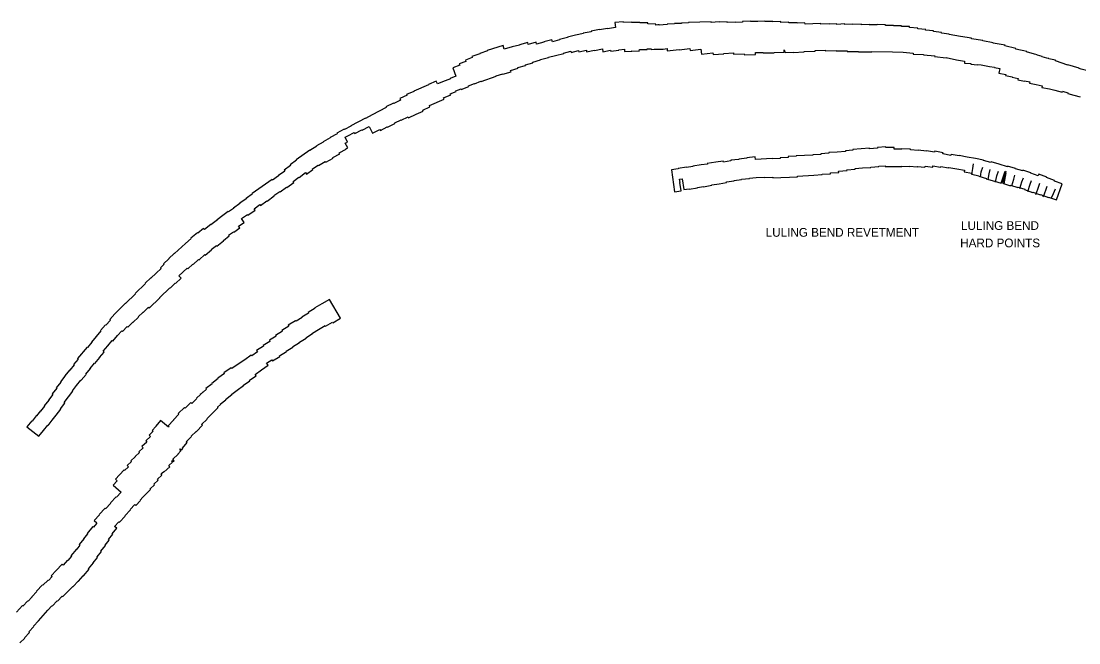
# Model space of a CAD drawing. Extents: x 2650582 to 3923188, y 277893 to 989177.
# Drawn here: x 3605630 to 3624994, y 526152 to 537540 of the extents above; entities that cross this region are included whole.
import ezdxf

# ---------------------------------------------------------------- set-up
doc = ezdxf.new("R2010")
doc.units = 0
doc.layers.add('Level 3', color=7, linetype='Continuous')

msp = doc.modelspace()

# ---------------------------------------------------------------- linework, layer by layer
at = {"layer": 'Level 3'}
msp.add_line((3623624, 534559), (3623666, 534762), dxfattribs=at)
for points in [[(3622480, 537319), (3622482, 537330), (3622332, 537353), (3622333, 537365), (3622189, 537376), (3622190, 537389), (3622045, 537400), (3622046, 537413), (3621895, 537423), (3621895, 537441), (3621748, 537443), (3621748, 537452), (3621602, 537456), (3621602, 537458), (3621457, 537461), (3621457, 537475), (3621301, 537479), (3621301, 537474), (3621157, 537474), (3621157, 537476), (3621013, 537475), (3621012, 537482), (3620858, 537480), (3620858, 537484), (3620712, 537477), (3620712, 537489), (3620565, 537481), (3620565, 537492), (3620420, 537484), (3620420, 537492), (3620273, 537484), (3620272, 537495), (3620127, 537488), (3620127, 537493), (3619981, 537486), (3619980, 537508), (3619835, 537503), (3619835, 537512), (3619687, 537506), (3619687, 537521), (3619540, 537517), (3619540, 537532), (3619393, 537525), (3619392, 537536), (3619247, 537532), (3619247, 537539), (3619116, 537534), (3619116, 537536), (3618985, 537531), (3618985, 537540), (3618838, 537534), (3618838, 537524), (3618703, 537518), (3618703, 537524), (3618558, 537517), (3618557, 537527), (3618411, 537519), (3618411, 537525), (3618265, 537518), (3618264, 537526), (3617848, 537513), (3617848, 537507), (3617717, 537504), (3617717, 537498), (3617589, 537495), (3617589, 537488), (3617455, 537483), (3617456, 537478), (3617310, 537469), (3617309, 537473), (3617309, 537473), (3617309, 537474), (3617287, 537471), (3617249, 537468)], [(3617249, 537468), (3617250, 537486), (3617103, 537491), (3617103, 537507), (3616958, 537510), (3616958, 537514), (3616807, 537517), (3616807, 537524), (3616655, 537516), (3616653, 537530), (3616500, 537513), (3616511, 537424), (3616367, 537400), (3616365, 537408), (3616217, 537381), (3616216, 537384), (3616064, 537355), (3616066, 537347), (3615921, 537320), (3615923, 537311), (3615782, 537283), (3615781, 537286), (3615630, 537248), (3615632, 537241), (3615485, 537203), (3615486, 537199), (3615357, 537164), (3615348, 537197), (3615198, 537158), (3615198, 537157), (3615066, 537121), (3615057, 537154), (3614913, 537115), (3614905, 537146), (3614756, 537106), (3614756, 537103), (3614622, 537067), (3614621, 537069), (3614476, 537029), (3614457, 537094), (3614163, 537005), (3614166, 536994), (3614025, 536947), (3614026, 536941), (3613880, 536891), (3613886, 536873), (3613764, 536824), (3613772, 536802), (3613652, 536756), (3613659, 536735), (3613532, 536687), (3613590, 536535), (3613486, 536489), (3613488, 536484), (3613391, 536446), (3613390, 536449), (3613251, 536391), (3613230, 536440), (3613086, 536378), (3613087, 536376), (3612820, 536258), (3612822, 536253), (3612688, 536198)], [(3624282, 536903), (3624232, 536919), (3624233, 536923), (3624184, 536934), (3624038, 536978), (3624040, 536983), (3623839, 537024), (3623842, 537041), (3623640, 537086), (3623643, 537097), (3623426, 537138), (3623427, 537142), (3623234, 537177), (3623235, 537185), (3623030, 537218), (3623031, 537226), (3622828, 537256), (3622829, 537261), (3622620, 537293), (3622621, 537299), (3622480, 537319)], [(3612063, 535485), (3612196, 535555), (3612207, 535535), (3612333, 535601), (3612335, 535598), (3612474, 535667), (3612470, 535675), (3612585, 535733), (3612588, 535726), (3612713, 535790), (3612722, 535771), (3612860, 535836), (3612991, 535892), (3612983, 535912), (3613114, 535970), (3613105, 535995), (3613375, 536110), (3613364, 536138), (3613494, 536189), (3613487, 536208), (3613594, 536253), (3613590, 536263), (3613683, 536301), (3613688, 536286), (3613825, 536340), (3613821, 536353), (3613930, 536396), (3613931, 536394), (3614047, 536441), (3614049, 536436), (3614325, 536530), (3614324, 536536), (3614447, 536577), (3614450, 536570), (3614599, 536613), (3614592, 536638), (3614729, 536677), (3614726, 536689), (3614865, 536728), (3614863, 536739), (3615000, 536776), (3614996, 536790), (3615141, 536831), (3615140, 536835), (3615283, 536874), (3615282, 536878), (3615412, 536912), (3615413, 536910), (3615563, 536948), (3615561, 536955), (3615691, 536990), (3615697, 536968), (3615833, 537003), (3615839, 536977), (3615978, 537006), (3615983, 536980), (3616124, 537008), (3616125, 537004), (3616271, 537032), (3616282, 536978), (3616422, 537006), (3616425, 536989), (3616572, 537010), (3616572, 537016), (3616674, 537029), (3616676, 536983), (3616809, 536989), (3616809, 536994), (3616946, 536990), (3616948, 537021), (3617092, 537018), (3617093, 537033), (3617163, 537031), (3617164, 537023), (3617217, 537029), (3617384, 537025), (3617384, 537029), (3617455, 537036)], [(3617455, 537036), (3617459, 536998), (3617676, 537020), (3617677, 537012), (3617875, 537037), (3617879, 537004), (3618075, 537025), (3618086, 536938), (3618294, 536958), (3618298, 536927), (3618493, 536943), (3618493, 536946), (3618673, 536959), (3618674, 536936), (3618869, 536944), (3618870, 536923), (3619074, 536926), (3619074, 536963)], [(3619074, 536963), (3619216, 536968), (3619216, 536960), (3619419, 536961), (3619419, 536966), (3619597, 536971), (3619597, 537013), (3619615, 536966), (3619764, 536972), (3619764, 536967), (3619963, 536975), (3619963, 536981), (3620169, 536987), (3620169, 537000), (3620350, 537006), (3620350, 536998), (3620551, 537000), (3620551, 536994), (3620754, 536996), (3620755, 536985), (3620958, 536986), (3620958, 536975), (3621174, 536975), (3621174, 536980), (3621205, 536978), (3621205, 536983), (3621580, 536975), (3621581, 536980), (3621775, 536969), (3621775, 536974), (3621961, 536955), (3621960, 536937), (3622153, 536926), (3622153, 536922), (3622355, 536905), (3622354, 536895), (3622567, 536867), (3622568, 536871), (3622756, 536834), (3622755, 536829), (3622902, 536804), (3622900, 536771), (3623017, 536763), (3623016, 536752), (3623139, 536739), (3623139, 536744), (3623207, 536737), (3623359, 536709), (3623360, 536712), (3623450, 536698), (3623449, 536690), (3623549, 536675)], [(3625365, 536560), (3625256, 536591), (3625256, 536591), (3625158, 536626), (3625158, 536628), (3625039, 536663), (3625038, 536659), (3624998, 536673), (3624999, 536678), (3624794, 536742), (3624791, 536736), (3624564, 536810), (3624567, 536823), (3624445, 536849), (3624445, 536853), (3624408, 536861), (3624322, 536889), (3624323, 536894), (3624282, 536903)], [(3623549, 536675), (3623530, 536588), (3623657, 536562), (3623654, 536547), (3623774, 536522), (3623772, 536512), (3623881, 536489), (3623876, 536466), (3623998, 536440), (3624000, 536449), (3624097, 536428), (3624092, 536406), (3624214, 536380), (3624214, 536381), (3624325, 536358), (3624318, 536327), (3624455, 536298), (3624456, 536302), (3624553, 536278), (3624552, 536274), (3624687, 536236), (3624693, 536256), (3624795, 536226), (3624793, 536217), (3624902, 536186), (3625021, 536152)], [(3612688, 536198), (3612695, 536182), (3612563, 536122), (3612575, 536094), (3612451, 536033), (3612448, 536040), (3612309, 535970), (3612314, 535958), (3612054, 535825), (3612055, 535823), (3611934, 535759), (3611932, 535763), (3611665, 535623), (3611667, 535618), (3611548, 535557), (3611546, 535560), (3611411, 535486), (3611415, 535477), (3611287, 535409), (3611290, 535402), (3611160, 535330), (3611161, 535326), (3611037, 535258), (3611042, 535248), (3610918, 535173), (3610915, 535177), (3610665, 535001), (3610670, 534993), (3610554, 534911), (3610563, 534898), (3610444, 534813), (3610457, 534794), (3610340, 534710), (3610342, 534706), (3610232, 534630), (3610226, 534638), (3609862, 534381), (3609865, 534376), (3609747, 534293), (3609751, 534287), (3609632, 534204), (3609636, 534199), (3609516, 534114), (3609519, 534110), (3609424, 534047), (3609422, 534051), (3609325, 533977), (3609323, 533978), (3609221, 533903), (3609223, 533900), (3609105, 533809), (3609101, 533813), (3608989, 533721), (3608971, 533744), (3608863, 533658), (3608856, 533665), (3608737, 533564), (3608742, 533558), (3608638, 533464), (3608439, 533281), (3608434, 533285), (3608333, 533191), (3608337, 533187), (3608234, 533095)], [(3608519, 532872), (3608670, 533014), (3608682, 533001), (3608774, 533089), (3608780, 533082), (3608880, 533177), (3608887, 533169), (3608991, 533264), (3609002, 533252), (3609117, 533349), (3609112, 533357), (3609205, 533431), (3609213, 533421), (3609336, 533518), (3609333, 533522), (3609441, 533606), (3609429, 533621), (3609516, 533681), (3609522, 533673), (3609632, 533752), (3609612, 533782), (3609712, 533852), (3609666, 533922), (3609775, 534000), (3609783, 533988), (3609912, 534079), (3609894, 534105), (3610000, 534182), (3610013, 534165), (3610130, 534249), (3610133, 534245), (3610261, 534338), (3610257, 534344), (3610366, 534422), (3610373, 534413), (3610489, 534499), (3610492, 534495), (3610620, 534585), (3610609, 534601), (3610717, 534681), (3610720, 534678), (3610834, 534765), (3610852, 534740), (3610972, 534824), (3610966, 534833), (3611068, 534902), (3611072, 534895), (3611198, 534972), (3611207, 534955), (3611341, 535032), (3611336, 535042), (3611463, 535112), (3611454, 535129), (3611579, 535197), (3611577, 535202), (3611608, 535219), (3611565, 535303), (3611607, 535325), (3611563, 535412), (3611611, 535438), (3611610, 535439), (3611727, 535502), (3611738, 535480), (3611867, 535548), (3611871, 535540), (3612001, 535609), (3612063, 535485)], [(3621164, 535211), (3621007, 535201), (3621007, 535199), (3620855, 535190), (3620856, 535174), (3620722, 535166), (3620722, 535152), (3620572, 535143), (3620572, 535142), (3620418, 535133), (3620419, 535119), (3620268, 535110), (3620268, 535100), (3620121, 535093), (3620121, 535087), (3619820, 535073), (3619821, 535065), (3619671, 535058), (3619672, 535041), (3619523, 535034), (3619523, 535026), (3619379, 535019), (3619379, 535023), (3619076, 535008), (3619071, 535052), (3618916, 535034), (3618917, 535029), (3618769, 535012), (3618770, 535008), (3618622, 534991), (3618624, 534979), (3618486, 534959), (3618483, 534976), (3618346, 534955), (3618346, 534956), (3618192, 534932), (3618194, 534922), (3618082, 534905), (3618082, 534906), (3617928, 534882), (3617929, 534876), (3617812, 534857), (3617811, 534863), (3617657, 534839), (3617658, 534832), (3617534, 534814)], [(3624585, 534265), (3624690, 534557), (3624546, 534609), (3624550, 534620), (3624404, 534673), (3624407, 534683), (3624262, 534735), (3624252, 534707), (3624116, 534756), (3624118, 534764), (3623971, 534809), (3623967, 534796), (3623836, 534836), (3623837, 534838), (3623690, 534884), (3623687, 534873), (3623533, 534922), (3623533, 534920), (3623387, 534961), (3623384, 534950), (3623249, 534988), (3623250, 534992), (3623100, 535027), (3623099, 535022), (3622948, 535051), (3622948, 535049), (3622802, 535078), (3622801, 535071), (3622654, 535100), (3622650, 535079), (3622504, 535108), (3622508, 535130), (3622355, 535156), (3622353, 535141), (3622206, 535163), (3622206, 535160), (3622052, 535177), (3622052, 535172), (3621910, 535183), (3621910, 535194), (3621754, 535201), (3621754, 535195), (3621610, 535197), (3621610, 535226), (3621462, 535228), (3621462, 535235), (3621305, 535226), (3621306, 535212), (3621164, 535203), (3621164, 535211)], [(3617534, 534814), (3617593, 534415), (3617711, 534433), (3617689, 534582), (3617694, 534582), (3617684, 534647), (3617731, 534654), (3617763, 534454), (3617857, 534469), (3617858, 534462), (3618011, 534486), (3618010, 534492), (3618122, 534509), (3618122, 534508), (3618276, 534533), (3618275, 534539), (3618408, 534561), (3618408, 534562), (3618545, 534583), (3618543, 534595), (3618683, 534616), (3618682, 534623), (3618819, 534638), (3618819, 534643), (3618966, 534659), (3618966, 534665), (3619089, 534679), (3619089, 534674), (3619240, 534681), (3619240, 534674), (3619391, 534681), (3619391, 534672), (3619540, 534679), (3619540, 534674), (3619696, 534681), (3619696, 534683), (3619845, 534690), (3619845, 534702), (3620145, 534716), (3620144, 534721), (3620295, 534728), (3620295, 534734), (3620447, 534744), (3620446, 534760), (3620598, 534769), (3620596, 534794), (3620750, 534803), (3620749, 534817), (3620900, 534826), (3620899, 534842), (3621033, 534850), (3621033, 534853), (3621185, 534862)], [(3621185, 534862), (3621184, 534868), (3621335, 534877), (3621334, 534881), (3621448, 534888), (3621448, 534879), (3621596, 534877), (3621753, 534875), (3621753, 534882), (3621896, 534876), (3621896, 534884), (3622037, 534873), (3622038, 534878), (3622175, 534863), (3622178, 534886), (3622232, 534878), (3622232, 534879), (3622318, 534866), (3622322, 534890), (3622464, 534866), (3622466, 534879), (3622610, 534851), (3622612, 534862), (3622760, 534833), (3622761, 534837), (3622901, 534810), (3622896, 534782), (3623036, 534754), (3623033, 534740), (3623165, 534709), (3623162, 534700), (3623303, 534660), (3623300, 534650), (3623448, 534608), (3623449, 534611), (3623574, 534572), (3623643, 534790), (3623660, 534785), (3623594, 534571), (3623740, 534526), (3623742, 534534), (3623879, 534491), (3623882, 534499), (3624004, 534461), (3624001, 534454), (3624147, 534402), (3624149, 534408), (3624290, 534358), (3624291, 534362), (3624438, 534309), (3624441, 534317), (3624585, 534265)], [(3623033, 534730), (3623053, 534839), (3623066, 534925)], [(3623192, 534681), (3623208, 534779), (3623236, 534868)], [(3623331, 534638), (3623350, 534742), (3623369, 534822)], [(3623468, 534593), (3623494, 534709), (3623523, 534791)], [(3623770, 534521), (3623801, 534647), (3623825, 534718)], [(3623916, 534474), (3623951, 534594), (3623978, 534671)], [(3624058, 534421), (3624102, 534554), (3624128, 534624)], [(3624206, 534367), (3624243, 534463), (3624279, 534570)], [(3624342, 534323), (3624363, 534378), (3624394, 534464), (3624412, 534516)], [(3624488, 534290), (3624527, 534382), (3624566, 534470)], [(3608234, 533095), (3608245, 533083), (3608181, 533021), (3608192, 533010), (3608103, 532924), (3608101, 532926), (3608006, 532835), (3608004, 532837), (3607903, 532740), (3607909, 532733), (3607719, 532550), (3607722, 532547), (3607538, 532369), (3607537, 532369), (3607437, 532272), (3607440, 532268), (3607348, 532179), (3607253, 532077), (3607265, 532065), (3607178, 531973), (3607172, 531978), (3607082, 531871), (3607088, 531866), (3607003, 531765), (3607005, 531763), (3606920, 531662), (3606923, 531660), (3606843, 531565), (3606836, 531570), (3606661, 531363), (3606674, 531351), (3606589, 531250), (3606599, 531242), (3606519, 531147), (3606517, 531149), (3606427, 531042), (3606431, 531038), (3606348, 530932), (3606355, 530927), (3606274, 530823), (3606283, 530816), (3606201, 530712), (3606212, 530704), (3606130, 530600), (3606135, 530596), (3606054, 530492), (3606059, 530488), (3605987, 530397), (3605982, 530401), (3605911, 530309), (3605907, 530312), (3605831, 530215), (3605823, 530220), (3605737, 530110)], [(3605737, 530110), (3605956, 529940), (3606037, 530044), (3606042, 530039), (3606118, 530137), (3606122, 530134), (3606198, 530232), (3606196, 530233), (3606269, 530324), (3606355, 530435), (3606352, 530437), (3606433, 530541), (3606418, 530553), (3606499, 530657), (3606497, 530658), (3606578, 530762), (3606569, 530770), (3606646, 530869), (3606725, 530964), (3606728, 530962), (3606818, 531069), (3606812, 531074), (3606897, 531175), (3606894, 531178), (3606973, 531273), (3606977, 531269), (3607068, 531376), (3607065, 531378), (3607150, 531479), (3607133, 531493), (3607218, 531594), (3607217, 531595), (3607297, 531690), (3607309, 531680), (3607392, 531779), (3607475, 531869), (3607487, 531858), (3607569, 531945), (3607581, 531933), (3607676, 532024), (3607678, 532022), (3607779, 532119), (3607774, 532124), (3607864, 532211), (3607868, 532207), (3607962, 532298), (3607976, 532283), (3608172, 532473), (3608168, 532476), (3608352, 532654), (3608358, 532649), (3608452, 532740), (3608457, 532736), (3608557, 532833), (3608519, 532872)], [(3611475, 532097), (3611273, 532444), (3611133, 532362), (3611134, 532361), (3611008, 532288), (3611012, 532281), (3610886, 532204), (3610894, 532191), (3610770, 532116), (3610775, 532109), (3610663, 532042), (3610656, 532052), (3610519, 531969), (3610529, 531951), (3610405, 531876), (3610416, 531859), (3610288, 531781), (3610296, 531768), (3610174, 531694), (3610186, 531675), (3610060, 531599), (3610067, 531586), (3609941, 531509), (3609956, 531483), (3609851, 531409), (3609843, 531421), (3609725, 531338), (3609725, 531339), (3609605, 531254), (3609603, 531258), (3609485, 531175), (3609474, 531189), (3609343, 531097), (3609353, 531083), (3609234, 531000), (3609237, 530995), (3609123, 530905), (3609128, 530899), (3609013, 530809)], [(3609236, 530461), (3609227, 530470), (3609280, 530515), (3609273, 530523), (3609378, 530606), (3609373, 530612), (3609488, 530702), (3609485, 530706), (3609588, 530778), (3609584, 530782), (3609703, 530866), (3609699, 530871), (3609817, 530954), (3609812, 530962), (3609931, 531046), (3609914, 531070), (3610031, 531154), (3610031, 531155), (3610150, 531239), (3610123, 531277), (3610220, 531335), (3610231, 531317), (3610369, 531400), (3610362, 531412), (3610488, 531488), (3610484, 531494), (3610606, 531567), (3610600, 531577), (3610729, 531654), (3610727, 531657), (3610850, 531732), (3610844, 531742), (3610967, 531817), (3610963, 531824), (3611076, 531892), (3611077, 531890), (3611197, 531963), (3611203, 531953), (3611328, 532026), (3611335, 532015), (3611475, 532097)], [(3609013, 530809), (3609023, 530796), (3608961, 530744), (3608959, 530746), (3608925, 530714), (3608910, 530701), (3608911, 530700), (3608842, 530633), (3608848, 530627), (3608757, 530538), (3608739, 530556), (3608633, 530453), (3608621, 530465), (3608507, 530351), (3608520, 530339), (3608417, 530236), (3608422, 530231), (3608320, 530129), (3608337, 530113), (3608329, 530105), (3608183, 530227), (3608093, 530120), (3608096, 530118), (3608027, 530044), (3608045, 530027), (3607971, 529956), (3607997, 529929), (3607913, 529854), (3607934, 529830), (3607842, 529750), (3607866, 529723), (3607787, 529649), (3607798, 529638), (3607718, 529563), (3607720, 529561), (3607640, 529486), (3607651, 529475), (3607571, 529401), (3607594, 529376), (3607525, 529312), (3607517, 529321), (3607430, 529232), (3607433, 529230), (3607359, 529148), (3607390, 529121), (3607317, 529040), (3607459, 528912), (3607377, 528823), (3607371, 528828), (3607266, 528714), (3607271, 528709), (3607177, 528607), (3607167, 528617), (3607061, 528504), (3607067, 528498), (3606968, 528391)], [(3607380, 528251), (3607340, 528284), (3607419, 528370), (3607430, 528360), (3607535, 528473), (3607529, 528479), (3607630, 528588), (3607624, 528593), (3607710, 528686), (3607731, 528667), (3607814, 528759), (3607809, 528763), (3607859, 528818), (3607859, 528818), (3607945, 528907), (3607943, 528909), (3608000, 528963), (3607990, 528974), (3608070, 529048), (3608059, 529060), (3608138, 529134), (3608125, 529149), (3608205, 529223), (3608189, 529239), (3608205, 529257), (3608204, 529258), (3608240, 529292), (3608247, 529285), (3608352, 529377), (3608333, 529399), (3608401, 529461), (3608384, 529479), (3608399, 529493), (3608416, 529474), (3608431, 529487), (3608406, 529515), (3608502, 529607), (3608499, 529611), (3608555, 529672), (3608537, 529689), (3608550, 529704), (3608569, 529686), (3608590, 529710), (3608584, 529716), (3608670, 529819), (3608653, 529833), (3608749, 529930), (3608744, 529935), (3608835, 530026), (3608838, 530023), (3608951, 530137), (3608934, 530154), (3609035, 530252), (3609028, 530258), (3609236, 530461)], [(3606968, 528391), (3607014, 528348), (3607009, 528342), (3607012, 528340), (3606956, 528272), (3606942, 528283), (3606839, 528158), (3606848, 528151), (3606771, 528058), (3606775, 528055), (3606691, 527953), (3606707, 527939), (3606647, 527866), (3606642, 527871), (3606540, 527747), (3606551, 527739), (3606483, 527663), (3606481, 527665), (3606400, 527574), (3606379, 527594), (3606269, 527478), (3606271, 527476), (3606181, 527381), (3606198, 527366), (3606131, 527295), (3606122, 527303), (3606030, 527206), (3606022, 527214), (3605911, 527097), (3605917, 527091), (3605823, 526992), (3605825, 526990), (3605756, 526918), (3605753, 526921), (3605663, 526827), (3605656, 526834), (3605545, 526717)], [(3605609, 526152), (3605697, 526238), (3605692, 526243), (3605786, 526342), (3605772, 526356), (3605863, 526452), (3605857, 526457), (3605949, 526555), (3605946, 526558), (3606035, 526652), (3606031, 526656), (3606120, 526750), (3606118, 526752), (3606192, 526830), (3606196, 526826), (3606288, 526924), (3606296, 526916), (3606384, 527009), (3606393, 527000), (3606483, 527095), (3606487, 527091), (3606577, 527186), (3606581, 527183), (3606675, 527282), (3606678, 527279), (3606768, 527381), (3606771, 527379), (3606877, 527499), (3606866, 527509), (3606953, 527615), (3606949, 527618), (3607029, 527716), (3607019, 527725), (3607101, 527825), (3607092, 527832), (3607176, 527934), (3607168, 527941), (3607244, 528034), (3607231, 528045), (3607310, 528141), (3607298, 528151), (3607380, 528251)]]:
    msp.add_lwpolyline(points, dxfattribs=at)

# ---------------------------------------------------------------- texts
for s, p in [('LULING BEND', (3622837, 533716)), ('LULING BEND REVETMENT', (3619261, 533591)), ('HARD POINTS', (3622822, 533397))]:
    msp.add_text(s, height=160, dxfattribs=at).set_placement(p)

doc.saveas('drawing.dxf')
